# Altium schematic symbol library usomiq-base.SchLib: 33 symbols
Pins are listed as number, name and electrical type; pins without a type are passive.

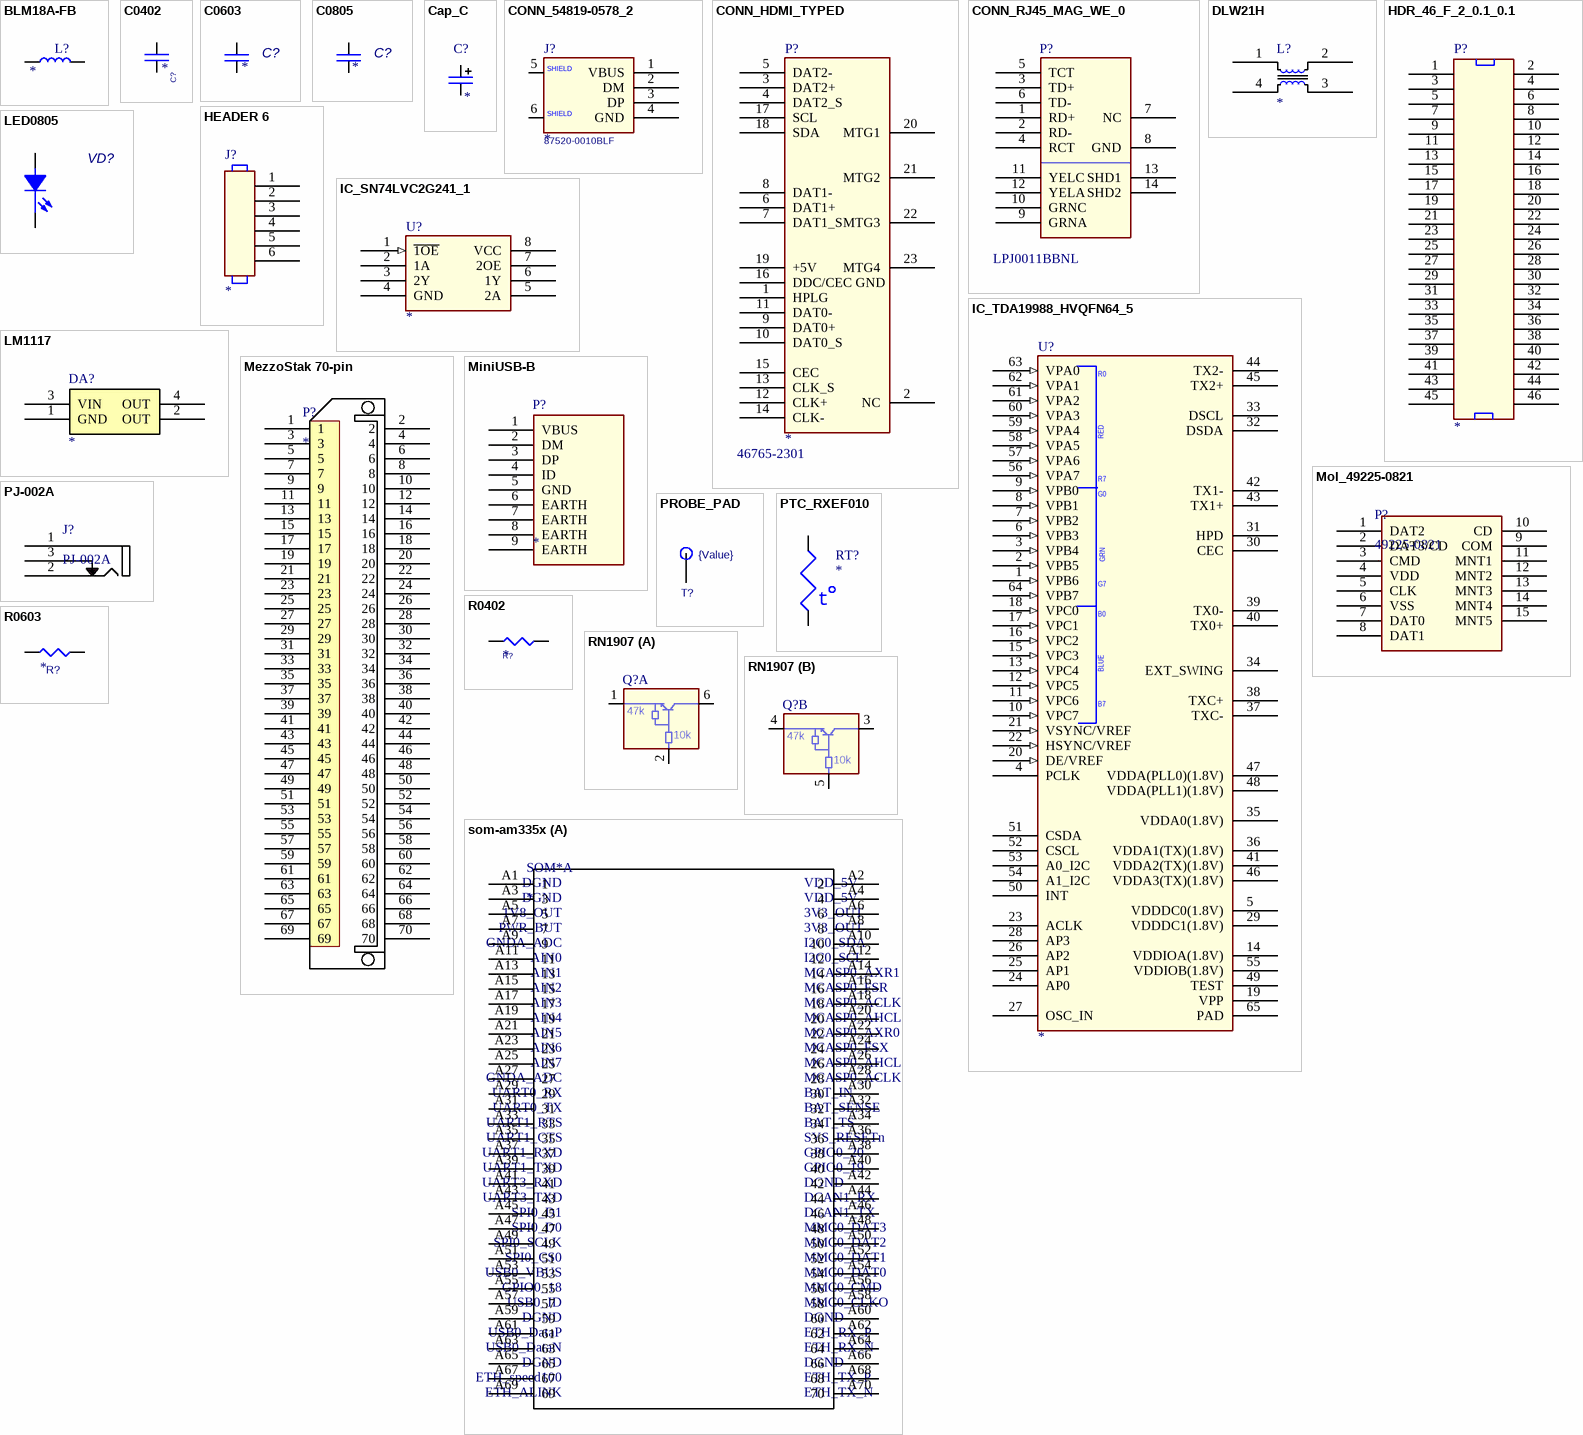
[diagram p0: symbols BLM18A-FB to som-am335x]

## BLM18A-FB
designator L?
Chip EMIFILr Inductor Type; Manufacturer: Murata
footprint CHIP0603
pins: 1, 2

## C0402
designator C?  (value not drawn)
footprint CC1005-0402 (Chip Capacitor, 2-Leads, Body 1,0x0,5mm, IPC Medium Density)
pins: 1, 2

## C0603
designator C?
C0603
footprint CC1608-0603 (Chip Capacitor, 2-Leads, Body 1,6x0,8mm, IPC Medium Density)
pins: 1, 2

## C0805
designator C?
C0805
footprint CC2012-0805 (Chip Capacitor, 2-Leads, Body 2,0x1,25mm, IPC Medium Density)
pins: 1, 2

## Cap_C
designator C?
Tantalum Capacitor Case C
footprint Cap_C (Capacitor, SM Tantalum; Body 6.0 x 3.2 mm (LxW typ))
pins: 1, 2

## CONN_54819-0578_2
designator J?  P/N: 87520-0010BLF
USB Type A Connectors; Mfr: FCI
footprint USB2.5-2H4C (Connector; USB1.1, Type A, Thru-Hole; 4 Position; Right Angle)
pins: 1 VBUS, 2 DM, 3 DP, 4 GND, 5 SHELD1, 6 PAD4

## CONN_HDMI_TYPED
designator P?  P/N: 46765-2301
Micro HDMI Connector, R/A; Mfr: Molex
footprint hdmi-smt-w-flange
pins: 1 HPLG, 2 NC, 3 DAT2+, 4 DAT2_S, 5 DAT2-, 6 DAT1+, 7 DAT1_S, 8 DAT1-, 9 DAT0+, 10 DAT0_S, 11 DAT0-, 12 CLK+, 13 CLK_S, 14 CLK-, 15 CEC, 16 DDC/CEC GND, 17 SCL, 18 SDA, 19 +5V, 20 MTG1 (power), 21 MTG2 (power), 22 MTG3 (power), 23 MTG4 (power)

## CONN_RJ45_MAG_WE_0
designator P?  P/N: LPJ0011BBNL  (hidden comment: *)
RJ-45 10/100 W/Magnetics; Mfr: Link PP; P/N-2: Wurth 7499011212
footprint TRJ0011ABNL (TRJ0011ABNL RJ-45 magnet)
pins: 1 RD+, 2 RD-, 3 TD+, 4 RCT, 5 TCT, 6 TD-, 7 NC, 8 GND, 9 GRNA, 10 GRNC, 11 YELC, 12 YELA, 13 SHD1, 14 SHD2

## DLW21H
designator L?
Low profile wire-wound common choke coil; Manufacturer: Murata; Man P/N: DLW21HN900SQ2
footprint DLW21H (DLW21H Series Murata)
pins: 1, 2, 3, 4

## HDR_46_F_2_0.1_0.1
designator P?
NN HEADER FMAL 46PS.1" DL GOLD; Mfr: major league electronics; P/N: SSHS-123-D-02-GT-LF
footprint DIP46
pins: 1, 2 26, 3 2, 4 27, 5 3, 6 28, 7 4, 8 29, 9 5, 10 30, 11 6, 12 31, 13 7, 14 32, 15 8, 16 33, 17 9, 18 34, 19 10, 20 35, 21 11, 22 36, 23 12, 24 37, 25 13, 26 38, 27 14, 28 39, 29 15, 30 40, 31 16, 32 41, 33 17, 34 42, 35 18, 36 43, 37 19, 38 44, 39 20, 40 45, 41 21, 42 46, 43 22, 44 47, 45 23, 46 48

## HEADER 6
designator J?
CONN HEADER 6POS, VERTICAL,  .100 STR TIN; Mfr: FCI; P/N: 68000-406HLF
footprint DIP6
pins: 1, 2, 3, 4, 5, 6

## IC_SN74LVC2G241_1
designator U?
Dual Buffer/Driver With 3-State Outputs; Mfr: TI; P/N: SN74LVC2G241DCU
footprint SOP127P600-8N
pins: 1 ~{1OE} (in), 2 1A, 3 2Y, 4 GND (power), 5 2A, 6 1Y, 7 2OE, 8 VCC (power)

## IC_TDA19988_HVQFN64_5
designator U?
IC HDMI INTERFACE HVQFN64; Mfr: NXP; P/N: TDA19988BHN/C1,551
pins: 1 VPB6 (in), 2 VPB5 (in), 3 VPB4 (in), 4 PCLK, 5 VDDDC0(1.8V) (power), 6 VPB3 (in), 7 VPB2 (in), 8 VPB1 (in), 9 VPB0 (in), 10 VPC7 (in), 11 VPC6 (in), 12 VPC5 (in), 13 VPC4 (in), 14 VDDIOA(1.8V) (power), 15 VPC3 (in), 16 VPC2 (in), 17 VPC1 (in), 18 VPC0 (in), 19 VPP (power), 20 DE/VREF (in), 21 VSYNC/VREF (in), 22 HSYNC/VREF (in), 23 ACLK, 24 AP0, 25 AP1, 26 AP2, 27 OSC_IN, 28 AP3, 29 VDDDC1(1.8V) (power), 30 CEC, 31 HPD, 32 DSDA, 33 DSCL, 34 EXT_SWING, 35 VDDA0(1.8V) (power), 36 VDDA1(TX)(1.8V) (power), 37 TXC-, 38 TXC+, 39 TX0-, 40 TX0+, 41 VDDA2(TX)(1.8V) (power), 42 TX1-, 43 TX1+, 44 TX2-, 45 TX2+, 46 VDDA3(TX)(1.8V) (power), 47 VDDA(PLL0)(1.8V) (power), 48 VDDA(PLL1)(1.8V) (power), 49 TEST (power), 50 INT, 51 CSDA, 52 CSCL, 53 A0_I2C (power), 54 A1_I2C (power), 55 VDDIOB(1.8V), 56 VPA7 (in), 57 VPA6 (in), 58 VPA5 (in), 59 VPA4 (in), 60 VPA3 (in), 61 VPA2 (in), 62 VPA1 (in), 63 VPA0 (in), 64 VPB7 (in), 65 PAD

## LED0805
designator VD?  (value not drawn)
LED 0805
footprint LED0805 (Chip LED, 2-Leads, Body 2,0x1,3mm, IPC Medium Density)
pins: 1 A, 2 C

## LM1117
designator DA?
800mA Low-Dropout Linear Regulator; Manufacturer: National; Man P/N: LM1117IMPX-3.3
footprint SOT230P700X160-4N (SOT223, 4-Leads, Body 6,7x7,3mm (max), Pitch 2,30mm, IPC Medium Density)
pins: 1 GND (power), 2 OUT (power), 3 VIN (power), 4 OUT (power)

## MezzoStak 70-pin
designator P?
MezzoStak 0.5 MM Mezzanine Connectors; Mfr: FCI; P/N: 10106813-071112LF
footprint 10106813-071112LF
pins: 1, 2, 3, 4, 5, 6, 7, 8, 9, 10, 11, 12, 13, 14, 15, 16, 17, 18, 19, 20, 21, 22, 23, 24, 25, 26, 27, 28, 29, 30, 31, 32, 33, 34, 35, 36, 37, 38, 39, 40, 41, 42, 43, 44, 45, 46, 47, 48, 49, 50, 51, 52, 53, 54, 55, 56, 57, 58, 59, 60, 61, 62, 63, 64, 65, 66, 67, 68, 69, 70

## MiniUSB-B
designator P?
Mini USB Type B CONNECTOR; Mfr: Hirose; P/N: UX60SC-MB-5ST(80)
footprint MINI-USB-B5 SMT
pins: 1 VBUS (power), 2 DM, 3 DP, 4 ID, 5 GND (power), 6 EARTH, 7 EARTH, 8 EARTH, 9 EARTH

## Mol_49225-0821
designator P?, comment 49225-0821
Connector for microSD™ Card (Push-push Type); Manufacturer: Molex
footprint SDCard (molex 0492250821)
pins: 1 DAT2, 2 DAT3/CD, 3 CMD, 4 VDD (power), 5 CLK, 6 VSS (power), 7 DAT0, 8 DAT1, 9 COM, 10 CD, 11 MNT1, 12 MNT2, 13 MNT3, 14 MNT4, 15 MNT5

## PJ-002A
designator J?
DC POWER JACK; Manufacturer: CIU Inc; Vendor: Digi-key; Alternative P/N: DJK-02A
footprint PJ-002A (DC POWER JACK)
pins: 1 GND, 2 RIGHT, 3 LEFT

## PROBE_PAD
designator T?  value {Value}  (hidden comment: *)
PROBE_PAD
footprint PAD
pins: 1

## PTC_RXEF010
designator RT?
PolySwitch Resettable Fuses; Mfr: TE Connectivity / Raychem; P/N: RXEF010
footprint polysw200-5638-310
pins: 1, 2

## R0402
designator R?  (value not drawn)
footprint RESC1005X40N (Chip Resistor, EIA 0402, Metric 1005, Body 1.0x0.5mm, IPC Medium Density)
pins: 1, 2

## R0603
designator R?
R0603
footprint RESC1608X55N (Chip Resistor, EIA 0603, Metric 1608, Body 1.6x0.8mm, IPC Medium Density)
pins: 1, 2

## RN1907
designator Q?  (value not drawn)
Transistor Silicon NPN; Mfr: Panasonic; P/N: DMC564040R
footprint SOT363-6L (SOT363, 6-Leads, Body 2x1.3mm, Pitch 0.65mm, Lead Span 2.1mm, IPC High Density)
part A pins: 1 4, 2 5, 6 3
part B pins: 3, 4, 5

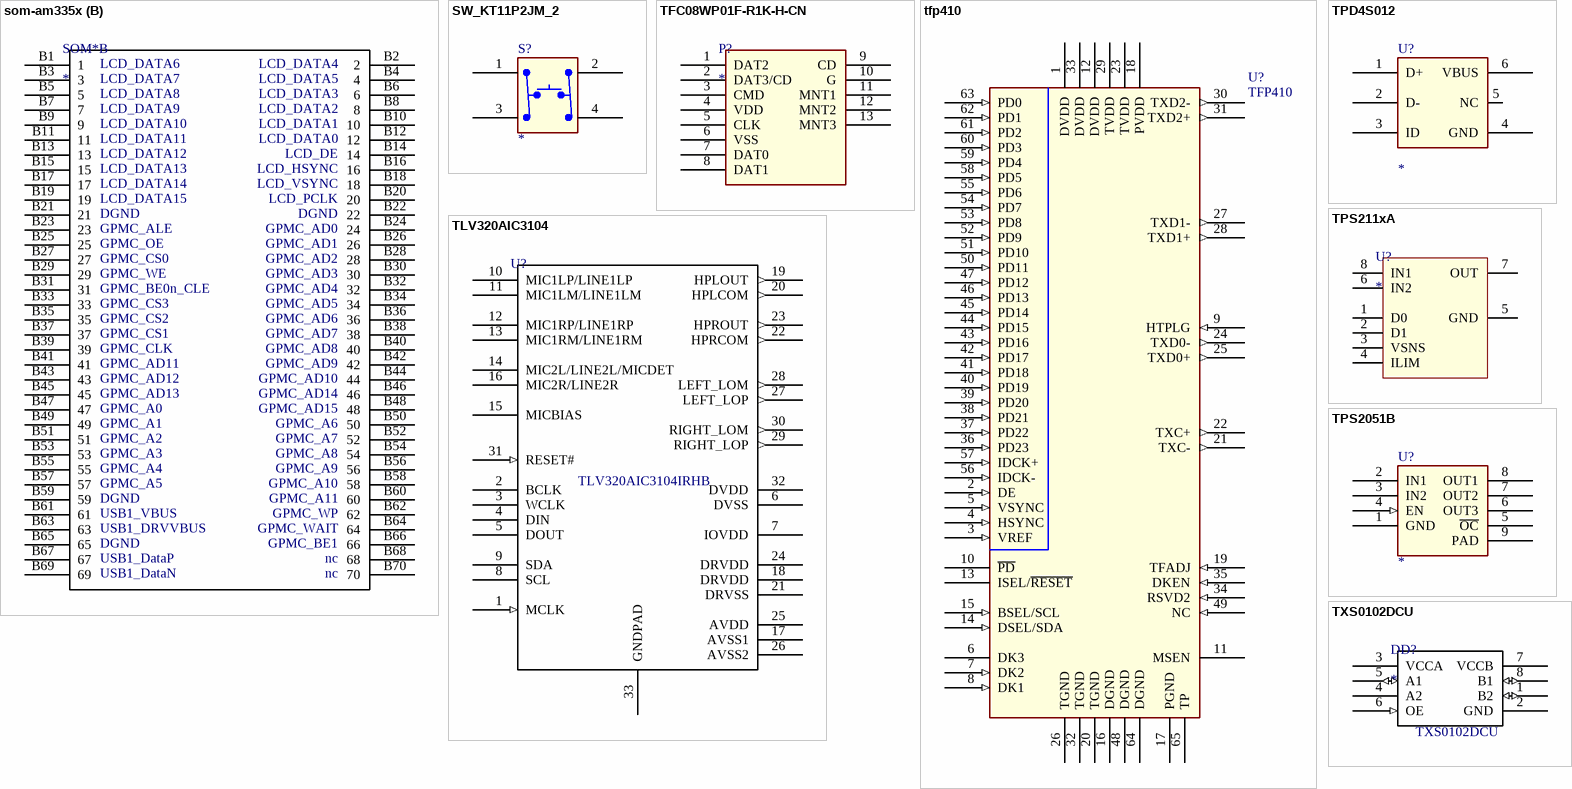
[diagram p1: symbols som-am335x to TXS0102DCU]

## som-am335x
designator SOM*
footprint am3359_module-sockets
part A pins: A1 1, A2 2, A3 3, A4 4, A5 5, A6 6, A7 7, A8 8, A9 9, A10 10, A11 11, A12 12, A13 13, A14 14, A15 15, A16 16, A17 17, A18 18, A19 19, A20 20, A21 21, A22 22, A23 23, A24 24, A25 25, A26 26, A27 27, A28 28, A29 29, A30 30, A31 31, A32 32, A33 33, A34 34, A35 35, A36 36, A37 37, A38 38, A39 39, A40 40, A41 41, A42 42, A43 43, A44 44, A45 45, A46 46, A47 47, A48 48, A49 49, A50 50, A51 51, A52 52, A53 53, A54 54, A55 55, A56 56, A57 57, A58 58, A59 59, A60 60, A61 61, A62 62, A63 63, A64 64, A65 65, A66 66, A67 67, A68 68, A69 69, A70 70
part B pins: B1 1, B2 2, B3 3, B4 4, B5 5, B6 6, B7 7, B8 8, B9 9, B10 10, B11 11, B12 12, B13 13, B14 14, B15 15, B16 16, B17 17, B18 18, B19 19, B20 20, B21 21, B22 22, B23 23, B24 24, B25 25, B26 26, B27 27, B28 28, B29 29, B30 30, B31 31, B32 32, B33 33, B34 34, B35 35, B36 36, B37 37, B38 38, B39 39, B40 40, B41 41, B42 42, B43 43, B44 44, B45 45, B46 46, B47 47, B48 48, B49 49, B50 50, B51 51, B52 52, B53 53, B54 54, B55 55, B56 56, B57 57, B58 58, B59 59, B60 60, B61 61, B62 62, B63 63, B64 64, B65 65, B66 66, B67 67, B68 68, B69 69, B70 70

## SW_KT11P2JM_2
designator S?
SMD button; Mfr: C&K Components; P/N: KMR231GLFS
footprint KMR231GLFS (Tactile Switches)
pins: 1 A1, 2 B1, 3 A2, 4 B2

## TFC08WP01F-R1K-H-CN
designator P?
Connector for microSD™ Card (Push-push Type); Mfr: AUK Contractors Co, LTD; P/N: TFC08WP01F-R1K-H-CN
footprint TFC08WP01F-A-R1K-H
pins: 1 DAT2, 2 DAT3/CD, 3 CMD, 4 VDD (power), 5 CLK, 6 VSS (power), 7 DAT0, 8 DAT1, 9 CD, 10 G, 11 MNT1, 12 MNT2, 13 MNT3

## tfp410
designator U?, comment TFP410
TI PanelBus digital transmitter; Man P/N: TFP410PAP
footprint PQFP64 (64-Pin Quad Flat Pad 0.5 mm Pitch, IPC Low Density)
pins: 1 DVDD (power), 2 DE (in), 3 VREF (in), 4 HSYNC (in), 5 VSYNC (in), 6 DK3, 7 DK2 (in), 8 DK1 (in), 9 HTPLG (in), 10 ~{PD}, 11 MSEN, 12 DVDD (power), 13 ISEL/~{RESET}, 14 DSEL/SDA (in), 15 BSEL/SCL (in), 16 DGND (power), 17 PGND (power), 18 PVDD (power), 19 TFADJ (in), 20 TGND (power), 21 TXC- (out), 22 TXC+ (out), 23 TVDD (power), 24 TXD0- (out), 25 TXD0+ (out), 26 TGND (power), 27 TXD1- (out), 28 TXD1+ (out), 29 TVDD (power), 30 TXD2- (out), 31 TXD2+ (out), 32 TGND (power), 33 DVDD (power), 34 RSVD2 (in), 35 DKEN (in), 36 PD23 (in), 37 PD22 (in), 38 PD21 (in), 39 PD20 (in), 40 PD19 (in), 41 PD18 (in), 42 PD17 (in), 43 PD16 (in), 44 PD15 (in), 45 PD14 (in), 46 PD13 (in), 47 PD12 (in), 48 DGND (power), 49 NC (in), 50 PD11 (in), 51 PD10 (in), 52 PD9 (in), 53 PD8 (in), 54 PD7 (in), 55 PD6 (in), 56 IDCK- (in), 57 IDCK+ (in), 58 PD5 (in), 59 PD4 (in), 60 PD3 (in), 61 PD2 (in), 62 PD1 (in), 63 PD0 (in), 64 DGND (power), 65 TP (power)

## TLV320AIC3104
designator U?  Man P/N: TLV320AIC3104IRHB  (hidden comment: *)
LOW-POWER STEREO AUDIO CODEC FOR PORTABLE AUDIO/TELEPHONY; Manufacturer: TI
footprint QFN32 (32-Pin Quad Flat No-Lead 0.5 mm Pitch, IPC Medium Density)
pins: 1 MCLK (in), 2 BCLK, 3 WCLK, 4 DIN, 5 DOUT, 6 DVSS (power), 7 IOVDD (power), 8 SCL, 9 SDA, 10 MIC1LP/LINE1LP, 11 MIC1LM/LINE1LM, 12 MIC1RP/LINE1RP, 13 MIC1RM/LINE1RM, 14 MIC2L/LINE2L/MICDET, 15 MICBIAS, 16 MIC2R/LINE2R, 17 AVSS1 (power), 18 DRVDD (power), 19 HPLOUT (out), 20 HPLCOM (out), 21 DRVSS (power), 22 HPRCOM (out), 23 HPROUT (out), 24 DRVDD (power), 25 AVDD (power), 26 AVSS2 (power), 27 LEFT_LOP (out), 28 LEFT_LOM (out), 29 RIGHT_LOP (out), 30 RIGHT_LOM (out), 31 RESET# (in), 32 DVDD (power), 33 GNDPAD (power)

## TPD4S012
designator U?
4-Channel USB ESD Solution with Power Clamp; Mfr: TI; P/N: TPD4S012DRYR
footprint s-puson-n6
pins: 1 D+, 2 D-, 3 ID, 4 GND (power), 5 NC, 6 VBUS (power)

## TPS211xA
designator U?
Single Channel, Current-Limited USB Power Distribution Switch; Manufacturer: TI
footprint TSSOP-8 (Shrink Small Outline; 8 Leads; Body Width 4.4 mm; Pitch 0.65 mm)
pins: 1 D0, 2 D1, 3 VSNS, 4 ILIM, 5 GND, 6 IN2, 7 OUT, 8 IN1

## TPS2051B
designator U?
CURRENT-LIMITED, POWER-DISTRIBUTION SWITCHES; Mfr: TI; P/N: TPS2051BDGN
footprint R-PDSO-G8
pins: 1 GND (power), 2 IN1 (power), 3 IN2 (power), 4 EN (in), 5 ~{OC}, 6 OUT3 (power), 7 OUT2 (power), 8 OUT1 (power), 9 PAD

## TXS0102DCU
designator DD?  Man P/N: TXS0102DCU
2bit Bidirectional voltage translator; Manufacturer: TI
footprint SOP127P600-8N
pins: 1 B2 (io), 2 GND (power), 3 VCCA (power), 4 A2 (power), 5 A1 (io), 6 OE (in), 7 VCCB (power), 8 B1 (io)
